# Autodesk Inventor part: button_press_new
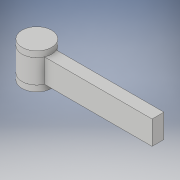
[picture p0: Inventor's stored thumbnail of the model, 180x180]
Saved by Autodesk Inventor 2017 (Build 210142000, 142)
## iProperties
Created: 2016-11
Part Number: button_press_new
Material: Generic
Document SubType Name: Modeling
Designer: radrajith
Density: 1 g/cm^3
Appearance: Default
Author: radrajith
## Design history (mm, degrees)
sketch "Sketch1"
  geometry: L1 (-22.945, 5)-(-22.945, 0); L2 (-22.945, 0)-(-8, 0); L3 (-8, 0)-(-8, 1.5); L4 (-8, 1.5)-(-4.792, 1.5); L5 (-8, 5)-(-8, 3.5); L6 (-8, 3.5)-(-4.792, 3.5); L7 (-8, 5)-(-22.945, 5); A1 r 2.5 centre (-2.5, 2.5) between (-4.792, 1.5) and (-4.792, 3.5); 1 further point
  constraints: 14 end point, 2 point on circle, 1 centre point, 1 parallel, 1 perpendicular, 1 point on line
  dimensions: "d1" = 5 distance of L1.end L1.start; "d2" = 1.5 distance of L2.end L3.end; "d3" = 1.5 distance of L5.end L5.start
extrude "Extrusion1" new body sketch "Sketch1" distance "d4" = 4; taper "d5" = 0 deg
sketch "Sketch6"
  geometry: L1 (0, 0)-(0, -4) reference; L2 (0, -4)-(14.962, -4); L3 (14.962, -4)-(14.962, 1); L4 (14.962, 1)-(0, 1); L5 (0, 1)-(0, -4); 1 further point
  constraints: 8 end point, 2 parallel, 1 horizontal, 1 perpendicular
extrude "Extrusion2" cut sketch "Sketch6" distance "d6" = 1.5; taper "d7" = 0 deg
sketch "Sketch7"
  geometry: C1 r 2.5 at (-2.5, 2.5); 1 further point
  constraints: 1 centre point
  dimensions: "d8" = 5 diameter of C1
extrude "Extrusion3" join sketch "Sketch7" distance "d9" = 1; taper "d10" = 0 deg
sketch "Sketch8"
  geometry: C1 r 2.5 at (2.5, 2.5); 1 further point
  constraints: 1 centre point
  dimensions: "d11" = 5 diameter of C1
extrude "Extrusion4" join sketch "Sketch8" distance "d12" = 1; taper "d13" = 0 deg
sketch "Sketch9"
  geometry: L1 (-3.208, 0)-(14.945, 0) reference; L2 (-0.128, 4)-(14.945, 4); L3 (14.945, 4)-(14.945, 0); L4 (14.945, 0)-(-0.128, 0); L5 (-0.128, 0)-(-0.128, 4); 1 further point
  constraints: 8 end point, 2 parallel, 1 horizontal, 1 perpendicular
extrude "Extrusion5" cut sketch "Sketch9" distance "d14" = 1.5; taper "d15" = 0 deg
body "Solid1"
